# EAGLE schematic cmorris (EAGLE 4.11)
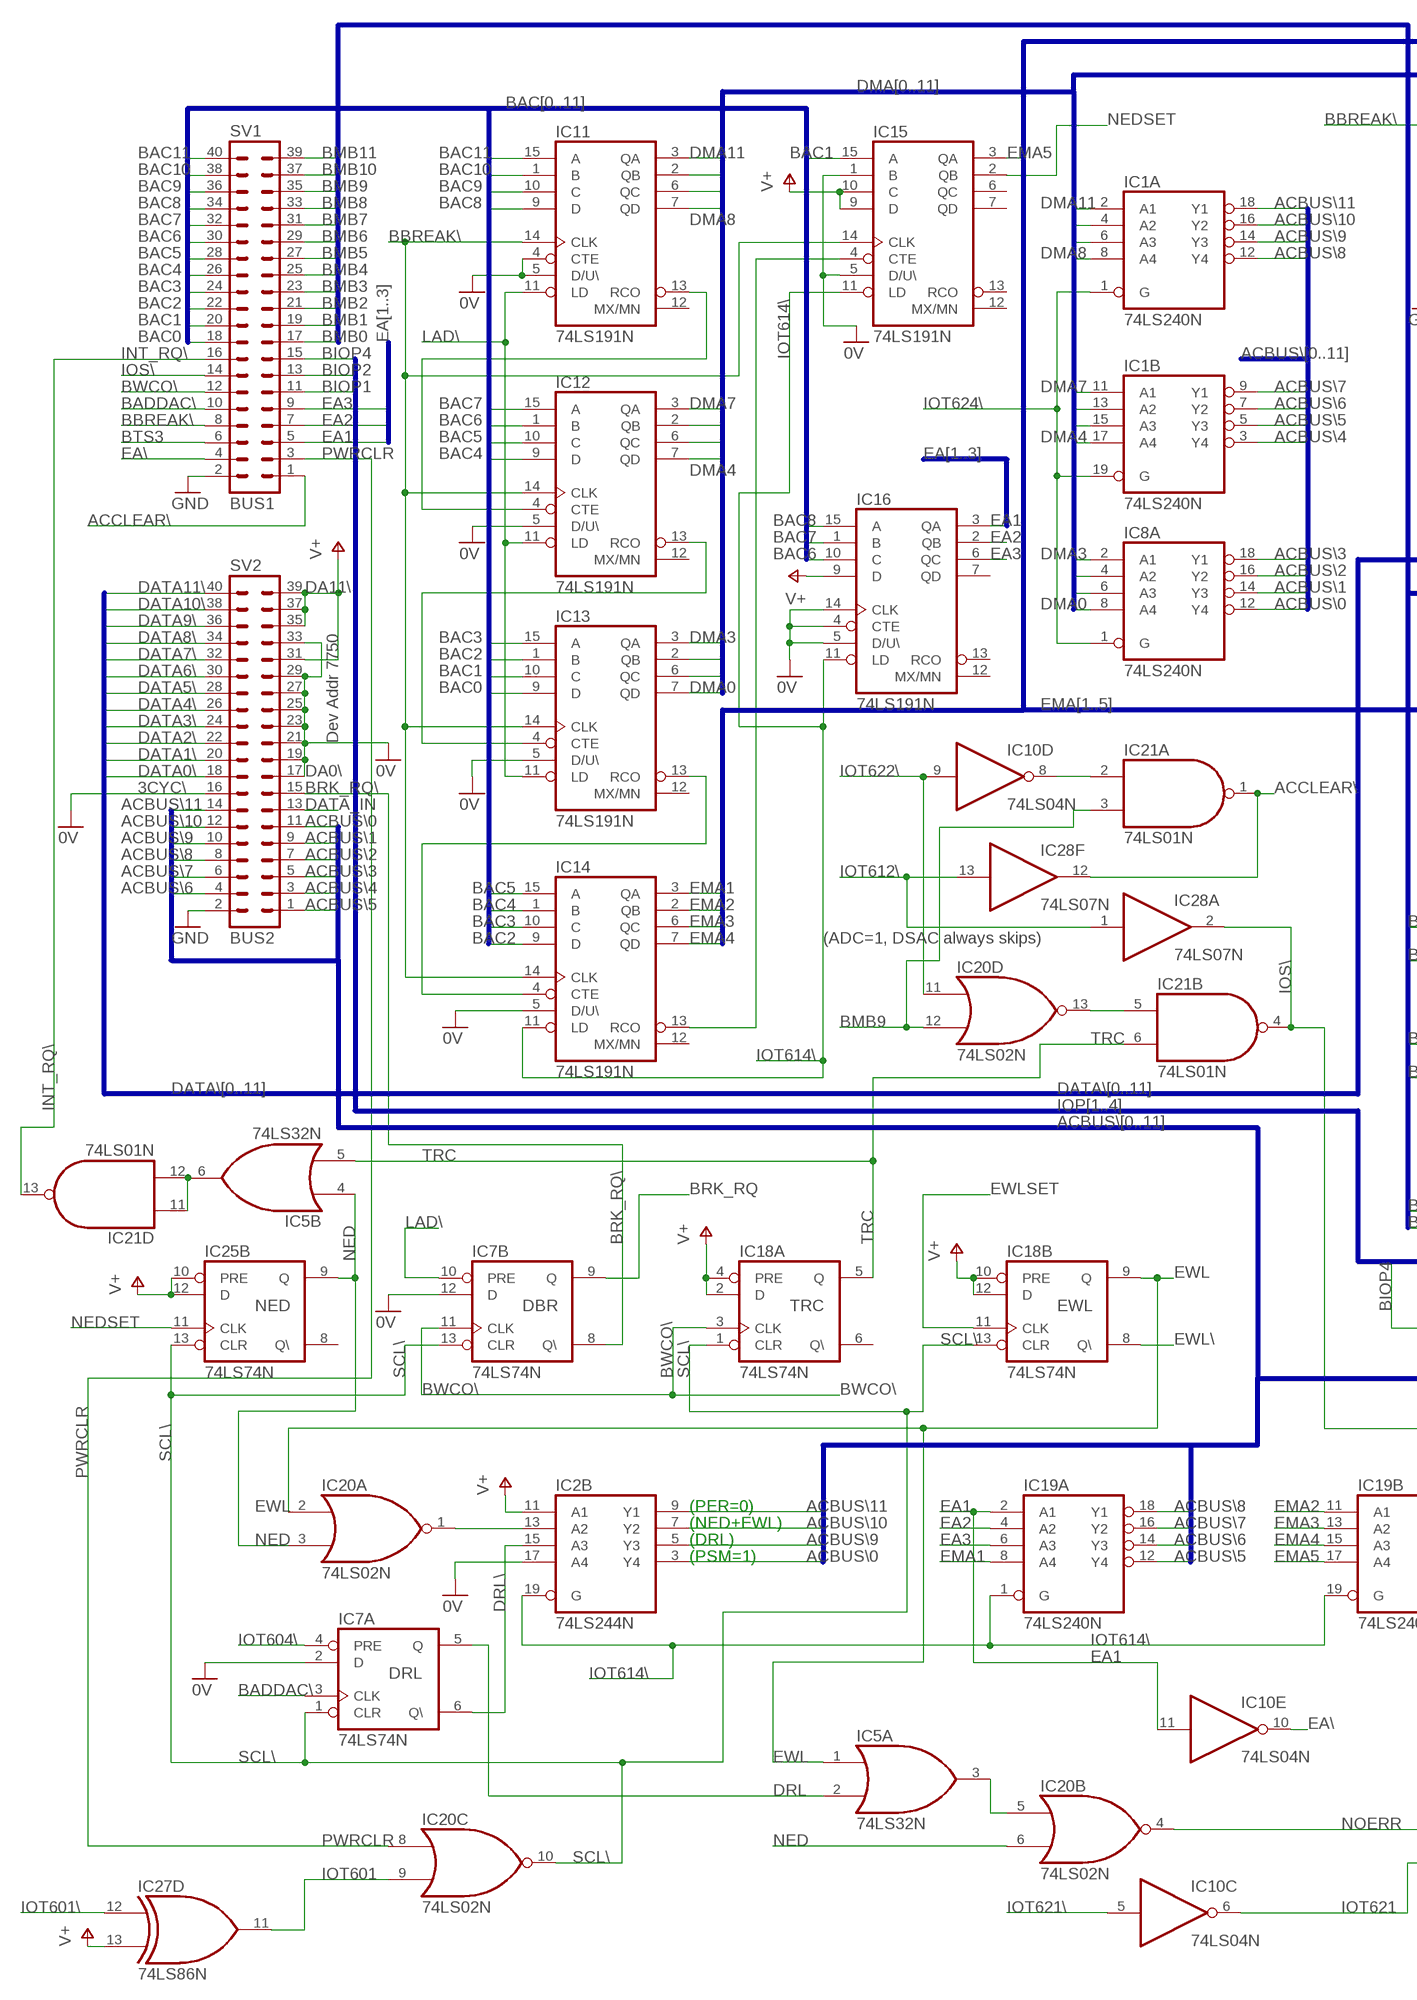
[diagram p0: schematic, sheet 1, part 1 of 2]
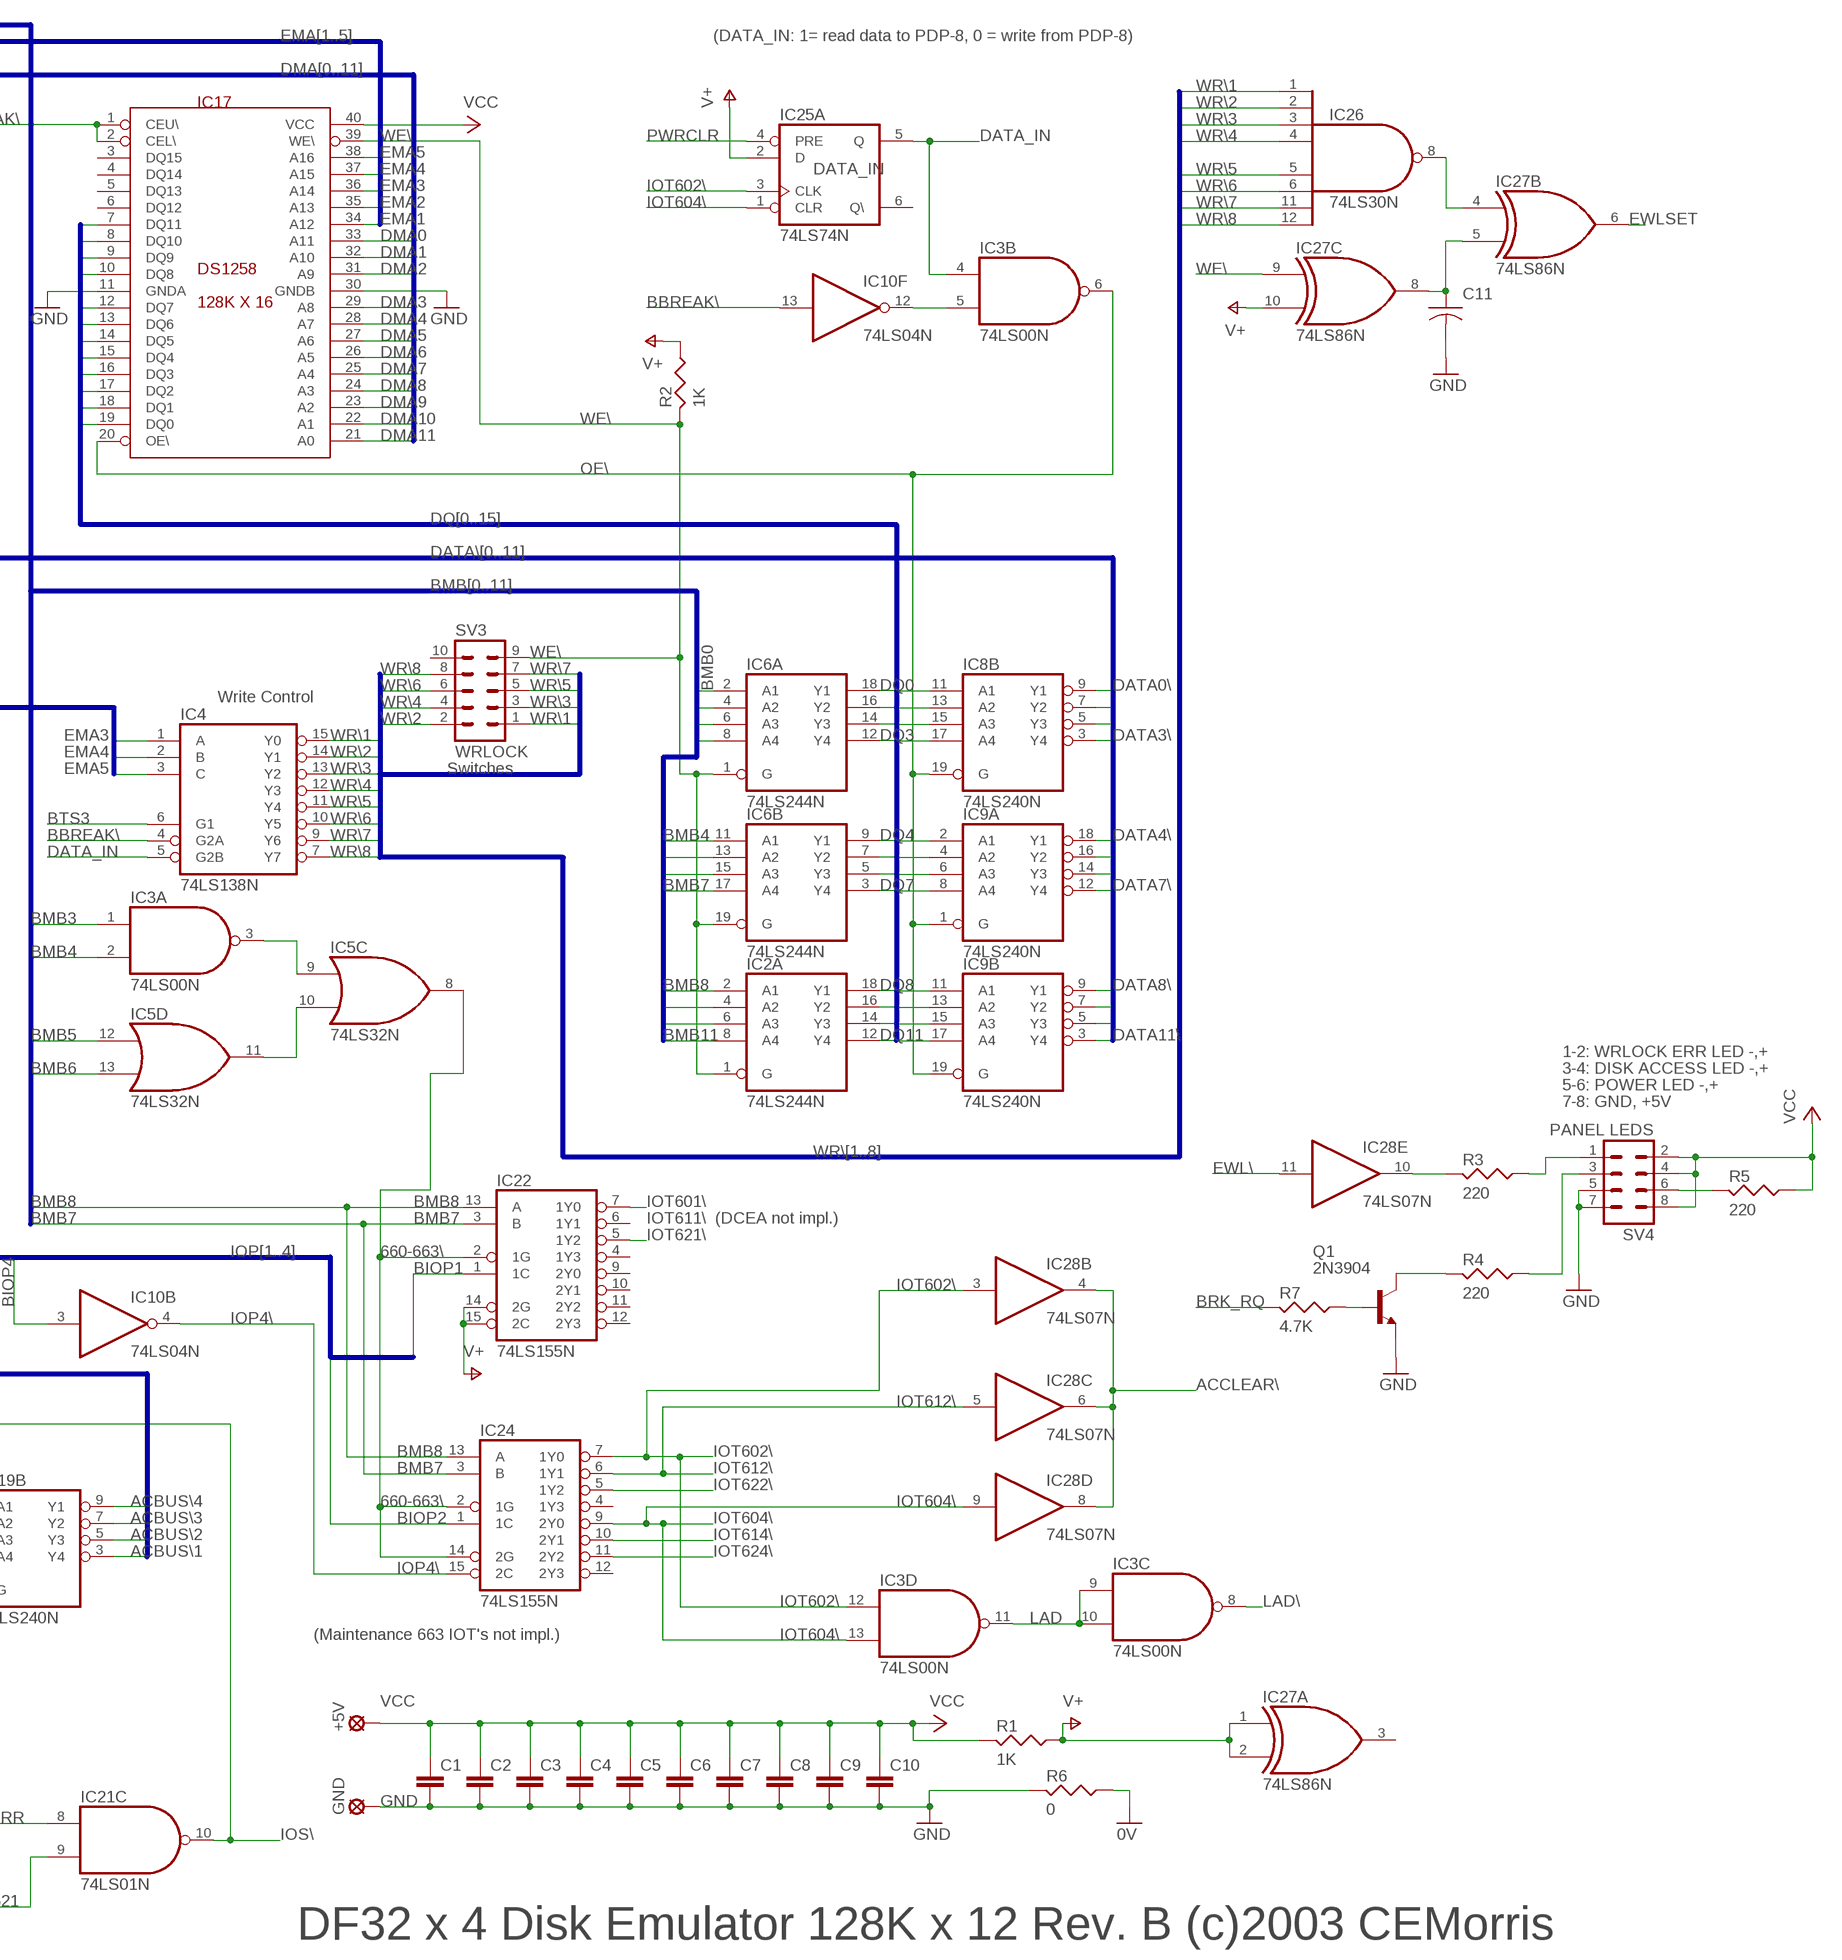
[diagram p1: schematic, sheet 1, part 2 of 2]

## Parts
+5V  SE14  [SE14]
C1  C5/3.5  [C5B3.5]
C2  C5/3.5  [C5B3.5]
C3  C5/3.5  [C5B3.5]
C4  C5/3.5  [C5B3.5]
C5  C5/3.5  [C5B3.5]
C6  C5/3.5  [C5B3.5]
C7  C5/3.5  [C5B3.5]
C8  C5/3.5  [C5B3.5]
C9  C5/3.5  [C5B3.5]
C10  C5/3.5  [C5B3.5]
C11  CAP-2,5  [C-2,5]
GND  SE14  [SE14]
IC1  74LS240N  [DIL20]
IC2  74LS244N  [DIL20]
IC3  74LS00N  [DIL14]
IC4  74LS138N  [DIL16]
IC5  74LS32N  [DIL14]
IC6  74LS244N  [DIL20]
IC7  74LS74N  [DIL14]
IC8  74LS240N  [DIL20]
IC9  74LS240N  [DIL20]
IC10  74LS04N  [DIL14]
IC11  74LS191N  74LS190N  [DIL16]
IC12  74LS191N  74LS190N  [DIL16]
IC13  74LS191N  74LS190N  [DIL16]
IC14  74LS191N  74LS190N  [DIL16]
IC15  74LS191N  74LS190N  [DIL16]
IC16  74LS191N  74LS190N  [DIL16]
IC17  DS1258  [DIL40]
IC18  74LS74N  [DIL14]
IC19  74LS240N  [DIL20]
IC20  74LS02N  [DIL14]
IC21  74LS01N  [DIL14]
IC22  74LS155N  [DIL16]
IC24  74LS155N  [DIL16]
IC25  74LS74N  [DIL14]
IC26  74LS30N  [DIL14]
IC27  74LS86N  [DIL14]
IC28  74LS07N  [DIL14]
Q1  2N3904  [TO92]
R1  1K  RESUS-5  [R-5]
R2  1K  RESUS-7,5  [R-7,5]
R3  220  RESUS-5  [R-5]
R4  220  RESUS-5  [R-5]
R5  220  RESUS-5  [R-5]
R6  0  RESUS-5  [R-5]
R7  4.7K  RESUS-5  [R-5]
SV1  BUS1  MA20-2  [MA20-2]
SV2  BUS2  MA20-2  [MA20-2]
SV3  WRLOCK  MA05-2  [MA05-2]
SV4  PANEL LEDS  MA04-2  [MA04-2]

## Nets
0V: IC2.17(B:A4) IC7.2(A:D) IC7.12(B:D) IC11.4(CTE) IC11.5(D/U\) IC12.5(D/U\) IC13.5(D/U\) IC14.5(D/U\) IC15.1(B) IC15.5(D/U\) IC16.4(CTE) IC16.5(D/U\) IC16.14(CLK) R6.1 SV2.16 SV2.17 SV2.19 SV2.21 SV2.23 SV2.25 SV2.27 SV2.29 SV2.33
660-663\: IC5.8(C:O) IC22.2(1G) IC24.2(1G) IC24.14(2G)
(NED+EWL)\: IC2.13(B:A2) IC20.1(A:O)
ACBUS\0: IC2.3(B:Y4) IC8.12(A:Y4) SV2.11
ACBUS\1: IC8.14(A:Y3) IC19.3(B:Y4) SV2.9
ACBUS\2: IC8.16(A:Y2) IC19.5(B:Y3) SV2.7
ACBUS\3: IC8.18(A:Y1) IC19.7(B:Y2) SV2.5
ACBUS\4: IC1.3(B:Y4) IC19.9(B:Y1) SV2.3
ACBUS\5: IC1.5(B:Y3) IC19.12(A:Y4) SV2.1
ACBUS\6: IC1.7(B:Y2) IC19.14(A:Y3) SV2.4
ACBUS\7: IC1.9(B:Y1) IC19.16(A:Y2) SV2.6
ACBUS\8: IC1.12(A:Y4) IC19.18(A:Y1) SV2.8
ACBUS\9: IC1.14(A:Y3) IC2.5(B:Y3) SV2.10
ACBUS\10: IC1.16(A:Y2) IC2.7(B:Y2) SV2.12
ACBUS\11: IC1.18(A:Y1) IC2.9(B:Y1) SV2.14
ACCLEAR\: IC21.1(A:O) IC28.4(B:O) IC28.6(C:O) IC28.8(D:O) IC28.12(F:O) SV1.1
BAC0: IC13.9(D) SV1.18
BAC1: IC13.10(C) IC15.15(A) SV1.20
BAC2: IC13.1(B) IC14.9(D) SV1.22
BAC3: IC13.15(A) IC14.10(C) SV1.24
BAC4: IC12.9(D) IC14.1(B) SV1.26
BAC5: IC12.10(C) IC14.15(A) SV1.28
BAC6: IC12.1(B) IC16.10(C) SV1.30
BAC7: IC12.15(A) IC16.1(B) SV1.32
BAC8: IC11.9(D) IC16.15(A) SV1.34
BAC9: IC11.10(C) SV1.36
BAC10: IC11.1(B) SV1.38
BAC11: IC11.15(A) SV1.40
BADDAC\: IC7.3(A:CLK) SV1.10
BBREAK\: IC4.4(G2A) IC10.13(F:I) IC11.14(CLK) IC12.14(CLK) IC13.14(CLK) IC14.14(CLK) IC15.14(CLK) IC17.1(CEU\) IC17.2(CEL\) SV1.8
BIOP1: IC22.1(1C) SV1.11
BIOP2: IC24.1(1C) SV1.13
BIOP4: IC10.3(B:I) SV1.15
BMB0: IC6.2(A:A1) SV1.17
BMB1: IC6.4(A:A2) SV1.19
BMB2: IC6.6(A:A3) SV1.21
BMB3: IC3.1(A:I0) IC6.8(A:A4) SV1.23
BMB4: IC3.2(A:I1) IC6.11(B:A1) SV1.25
BMB5: IC5.12(D:I0) IC6.13(B:A2) SV1.27
BMB6: IC5.13(D:I1) IC6.15(B:A3) SV1.29
BMB7: IC6.17(B:A4) IC22.3(B) IC24.3(B) SV1.31
BMB8: IC2.2(A:A1) IC22.13(A) IC24.13(A) SV1.33
BMB9: IC2.4(A:A2) IC20.12(D:I1) IC21.3(A:I1) SV1.35
BMB10: IC2.6(A:A3) SV1.37
BMB11: IC2.8(A:A4) SV1.39
BRK_RQ: IC7.9(B:Q) R7.2
BRK_RQ\: IC7.8(B:Q\) SV2.15
BTS3: IC4.6(G1) SV1.6
BWCO\: IC7.11(B:CLK) IC18.3(A:CLK) SV1.12
DATA0\: IC8.9(B:Y1) SV2.18
DATA1\: IC8.7(B:Y2) SV2.20
DATA2\: IC8.5(B:Y3) SV2.22
DATA3\: IC8.3(B:Y4) SV2.24
DATA4\: IC9.18(A:Y1) SV2.26
DATA5\: IC9.16(A:Y2) SV2.28
DATA6\: IC9.14(A:Y3) SV2.30
DATA7\: IC9.12(A:Y4) SV2.32
DATA8\: IC9.9(B:Y1) SV2.34
DATA9\: IC9.7(B:Y2) SV2.36
DATA10\: IC9.5(B:Y3) SV2.38
DATA11\: IC9.3(B:Y4) SV2.40
DATA_IN: IC3.4(B:I0) IC4.5(G2B) IC25.5(A:Q) SV2.13
DISK_LED: R4.1 SV4.3
DMA0: IC8.8(A:A4) IC13.7(QD) IC17.33(A11)
DMA1: IC8.6(A:A3) IC13.6(QC) IC17.32(A10)
DMA2: IC8.4(A:A2) IC13.2(QB) IC17.31(A9)
DMA3: IC8.2(A:A1) IC13.3(QA) IC17.29(A8)
DMA4: IC1.17(B:A4) IC12.7(QD) IC17.28(A7)
DMA5: IC1.15(B:A3) IC12.6(QC) IC17.27(A6)
DMA6: IC1.13(B:A2) IC12.2(QB) IC17.26(A5)
DMA7: IC1.11(B:A1) IC12.3(QA) IC17.25(A4)
DMA8: IC1.8(A:A4) IC11.7(QD) IC17.24(A3)
DMA9: IC1.6(A:A3) IC11.6(QC) IC17.23(A2)
DMA10: IC1.4(A:A2) IC11.2(QB) IC17.22(A1)
DMA11: IC1.2(A:A1) IC11.3(QA) IC17.21(A0)
DQ0: IC6.18(A:Y1) IC8.11(B:A1) IC17.19(DQ0)
DQ1: IC6.16(A:Y2) IC8.13(B:A2) IC17.18(DQ1)
DQ2: IC6.14(A:Y3) IC8.15(B:A3) IC17.17(DQ2)
DQ3: IC6.12(A:Y4) IC8.17(B:A4) IC17.16(DQ3)
DQ4: IC6.9(B:Y1) IC9.2(A:A1) IC17.15(DQ4)
DQ5: IC6.7(B:Y2) IC9.4(A:A2) IC17.14(DQ5)
DQ6: IC6.5(B:Y3) IC9.6(A:A3) IC17.13(DQ6)
DQ7: IC6.3(B:Y4) IC9.8(A:A4) IC17.12(DQ7)
DQ8: IC2.18(A:Y1) IC9.11(B:A1) IC17.10(DQ8)
DQ9: IC2.16(A:Y2) IC9.13(B:A2) IC17.9(DQ9)
DQ10: IC2.14(A:Y3) IC9.15(B:A3) IC17.8(DQ10)
DQ11: IC2.12(A:Y4) IC9.17(B:A4) IC17.7(DQ11)
DRL: IC5.2(A:I1) IC7.5(A:Q)
DRL\: IC2.15(B:A3) IC7.6(A:Q\)
EA1: IC10.11(E:I) IC16.3(QA) IC19.2(A:A1) SV1.5
EA2: IC16.2(QB) IC19.4(A:A2) SV1.7
EA3: IC16.6(QC) IC19.6(A:A3) SV1.9
EA\: IC10.10(E:O) SV1.4
EMA1: IC14.3(QA) IC17.34(A12) IC19.8(A:A4)
EMA2: IC14.2(QB) IC17.35(A13) IC19.11(B:A1)
EMA3: IC4.1(A) IC14.6(QC) IC17.36(A14) IC19.13(B:A2)
EMA4: IC4.2(B) IC14.7(QD) IC17.37(A15) IC19.15(B:A3)
EMA5: IC4.3(C) IC15.3(QA) IC17.38(A16) IC19.17(B:A4)
EWL: IC5.1(A:I0) IC18.9(B:Q) IC20.2(A:I0)
EWL\: IC18.8(B:Q\) IC28.11(E:I)
EWLSET: IC18.11(B:CLK) IC27.6(B:O)
GND [supply]: C1.2 C2.2 C3.2 C4.2 C5.2 C6.2 C7.2 C8.2 C9.2 C10.2 C11.2 GND.MP IC17.11(GNDA) IC17.30(GNDB) Q1.3(E) R6.2 SV1.2 SV2.2 SV4.5 SV4.7
INT_RQ\: IC21.13(D:O) SV1.16
IOP4\: IC10.4(B:O) IC24.15(2C)
IOS\: IC21.4(B:O) IC21.10(C:O) IC28.2(A:O) SV1.14
IOT601: IC20.9(C:I1) IC27.11(D:O)
IOT601\: IC22.7(1Y0) IC27.12(D:I0)
IOT602\: IC3.12(D:I0) IC24.7(1Y0) IC25.3(A:CLK) IC28.3(B:I)
IOT604\: IC3.13(D:I1) IC7.4(A:PRE) IC24.9(2Y0) IC25.1(A:CLR) IC28.9(D:I)
IOT612\: IC24.6(1Y1) IC28.1(A:I) IC28.5(C:I) IC28.13(F:I)
IOT614\: IC2.19(B:G) IC14.11(LD) IC15.11(LD) IC16.11(LD) IC19.1(A:G) IC19.19(B:G) IC24.10(2Y1)
IOT621: IC10.6(C:O) IC21.9(C:I1)
IOT621\: IC10.5(C:I) IC22.5(1Y2)
IOT622\: IC10.9(D:I) IC20.11(D:I0) IC24.5(1Y2)
IOT624\: IC1.1(A:G) IC1.19(B:G) IC8.1(A:G) IC24.11(2Y2)
LAD: IC3.9(C:I0) IC3.10(C:I1) IC3.11(D:O)
LAD\: IC3.8(C:O) IC7.10(B:PRE) IC11.11(LD) IC12.11(LD) IC13.11(LD)
N$1: C11.1 IC27.5(B:I1) IC27.8(C:O)
N$2: IC5.6(B:O) IC21.11(D:I0) IC21.12(D:I1)
N$3: IC28.10(E:O) R3.2
N$4: IC3.5(B:I1) IC10.12(F:O)
N$5: Q1.1(C) R4.2
N$6: R5.2 SV4.6
N$10: IC13.13(RCO) IC14.4(CTE)
N$11: IC12.13(RCO) IC13.4(CTE)
N$12: IC11.13(RCO) IC12.4(CTE)
N$13: IC3.3(A:O) IC5.9(C:I0)
N$14: IC14.13(RCO) IC15.4(CTE)
N$15: IC5.10(C:I1) IC5.11(D:O)
N$17: IC20.13(D:O) IC21.5(B:I0)
N$19: IC5.3(A:O) IC20.5(B:I0)
N$21: IC10.8(D:O) IC21.2(A:I0)
N$22: IC26.8(O) IC27.4(B:I0)
N$23: Q1.2(B) R7.1
NED: IC5.4(B:I0) IC20.3(A:I1) IC20.6(B:I1) IC25.9(B:Q)
NEDSET: IC15.2(QB) IC25.11(B:CLK)
NOERR: IC20.4(B:O) IC21.8(C:I0)
OE\: IC3.6(B:O) IC8.19(B:G) IC9.1(A:G) IC9.19(B:G) IC17.20(OE\)
PWRCLR: IC20.8(C:I0) IC25.4(A:PRE) SV1.3
SCL\: IC7.1(A:CLR) IC7.13(B:CLR) IC18.1(A:CLR) IC18.13(B:CLR) IC20.10(C:O) IC25.13(B:CLR)
TRC: IC5.5(B:I1) IC18.5(A:Q) IC21.6(B:I1)
V+: IC2.11(B:A1) IC15.9(D) IC15.10(C) IC16.9(D) IC18.2(A:D) IC18.4(A:PRE) IC18.10(B:PRE) IC18.12(B:D) IC22.14(2G) IC22.15(2C) IC25.2(A:D) IC25.10(B:PRE) IC25.12(B:D) IC27.1(A:I0) IC27.2(A:I1) IC27.10(C:I1) IC27.13(D:I1) R1.1 R2.1 SV2.31 SV2.35 SV2.37 SV2.39
VCC [supply]: +5V.MP C1.1 C2.1 C3.1 C4.1 C5.1 C6.1 C7.1 C8.1 C9.1 C10.1 IC17.40(VCC) R1.2 R5.1 SV4.2 SV4.4 SV4.8
WE\: IC2.1(A:G) IC6.1(A:G) IC6.19(B:G) IC17.39(WE\) IC27.9(C:I0) R2.2 SV3.9
WR\1: IC4.15(Y0) IC26.1(I0) SV3.1
WR\2: IC4.14(Y1) IC26.2(I1) SV3.2
WR\3: IC4.13(Y2) IC26.3(I2) SV3.3
WR\4: IC4.12(Y3) IC26.4(I3) SV3.4
WR\5: IC4.11(Y4) IC26.5(I4) SV3.5
WR\6: IC4.10(Y5) IC26.6(I5) SV3.6
WR\7: IC4.9(Y6) IC26.11(I6) SV3.7
WR\8: IC4.7(Y7) IC26.12(I7) SV3.8
WRITELOCK_LED: R3.1 SV4.1
Unconnected: IC10.1(A:I) IC10.2(A:O) IC11.12(MX/MN) IC12.12(MX/MN) IC13.12(MX/MN) IC14.12(MX/MN) IC15.6(QC) IC15.7(QD) IC15.12(MX/MN) IC15.13(RCO) IC16.7(QD) IC16.12(MX/MN) IC16.13(RCO) IC17.3(DQ15) IC17.4(DQ14) IC17.5(DQ13) IC17.6(DQ12) IC18.6(A:Q\) IC22.4(1Y3) IC22.6(1Y1) IC22.9(2Y0) IC22.10(2Y1) IC22.11(2Y2) IC22.12(2Y3) IC24.4(1Y3) IC24.12(2Y3) IC25.6(A:Q\) IC25.8(B:Q\) IC27.3(A:O) SV3.10

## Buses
BAC[0..11]
DATA\[0..11]
DMA[0..11]
EMA[1..5]
BMB[0..11]
EMA[3..5]
DQ[0..15]
IOP[1..4]
ACBUS\[0..11]
EA[1..3]
WR\[1..8]

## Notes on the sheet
- (DATA_IN: 1= read data to PDP-8, 0 = write from PDP-8)
- DATA_IN
- DA11\
- Write Control
- Dev Addr 7750
- DA0\ | Switches
- 3CYC\
- (ADC=1, DSAC always skips)
- 1-2: WRLOCK ERR LED -,+
- 3-4: DISK ACCESS LED -,+
- 5-6: POWER LED -,+
- 7-8: GND, +5V
- IOT611\  (DCEA not impl.)
- NED | DBR | TRC | EWL
- (PER=0)
- (NED+EWL)
- (DRL)
- (PSM=1)
- (Maintenance 663 IOT's not impl.)
- DRL
- DF32 x 4 Disk Emulator 128K x 12 Rev. B (c)2003 CEMorris

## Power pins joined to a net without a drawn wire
GND: IC1.10(P:GND) IC2.10(P:GND) IC3.7(P:GND) IC4.8(GND) IC5.7(P:GND) IC6.10(P:GND) IC7.7(P:GND) IC8.10(P:GND) IC9.10(P:GND) IC10.7(P:GND) IC11.8(GND) IC12.8(GND) IC13.8(GND) IC14.8(GND) IC15.8(GND) IC16.8(GND) IC18.7(P:GND) IC19.10(P:GND) IC20.7(P:GND) IC21.7(P:GND) IC22.8(GND) IC24.8(GND) IC25.7(P:GND) IC26.7(GND) IC27.7(P:GND) IC28.7(P:GND)
VCC: IC1.20(P:VCC) IC2.20(P:VCC) IC3.14(P:VCC) IC4.16(VCC) IC5.14(P:VCC) IC6.20(P:VCC) IC7.14(P:VCC) IC8.20(P:VCC) IC9.20(P:VCC) IC10.14(P:VCC) IC11.16(VCC) IC12.16(VCC) IC13.16(VCC) IC14.16(VCC) IC15.16(VCC) IC16.16(VCC) IC18.14(P:VCC) IC19.20(P:VCC) IC20.14(P:VCC) IC21.14(P:VCC) IC22.16(VCC) IC24.16(VCC) IC25.14(P:VCC) IC26.14(VCC) IC27.14(P:VCC) IC28.14(P:VCC)

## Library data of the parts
+5V GND = solpad:SE14: SOLDER PAD
C1-C10 = capacitor-wima:C: CAPACITOR
C11 = discrete:CAP-2,5
IC1 IC8 IC9 IC19 = 74xx-us:74*240: Octal BUFFER and LINE DRIVER, 3-state
IC2 IC6 = 74xx-us:74*244: Octal BUFFER and LINE DRIVER, 3-state
IC3 = 74xx-us:74*00: Quad 2-input NAND gate
IC4 = 74xx-us:74*138: 3-line to 8-line DECODER/DEMULTIPLEXER
IC5 = 74xx-us:74*32: Quad 2-input OR gate
IC7 IC18 IC25 = 74xx-us:74*74: Dual D type positive edge triggered FLIP FLOP, preset and clear
IC10 = 74xx-us:74*04: Hex INVERTER
IC11-IC16 = 74xx-us:74*190: Synchronous UP/DOWN COUNTER
IC17 = maxim:DS1258: DS1258 128K x 16 NVRAM
IC20 = 74xx-us:74*02: Quad 2-input NOR gate
IC21 = 74xx-us:74*01: Quad 2-input NAND gate, open collector
IC22 IC24 = 74xx-us:74*155: Dual 2-line to 4-line data DECODER/DEMULTIPLEXER
IC26 = 74xx-us:74*30: 8-input NAND gate
IC27 = 74xx-us:74*86: Quad 2-input EXCLUSIV-OR (XOR) gate
IC28 = 74xx-us:74*07: Hex BUFFER, open collector high-voltage output
Q1 = transistor-npn:2N3904: NPN Transistor
R1 R3-R7 = discrete:RESUS-5
R2 = discrete:RESUS-7,5
SV1 SV2 = con-lstb:MA20-2: PIN HEADER
SV3 = con-lstb:MA05-2: PIN HEADER
SV4 = con-lstb:MA04-2: PIN HEADER

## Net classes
1 supply: width 1.016 mm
